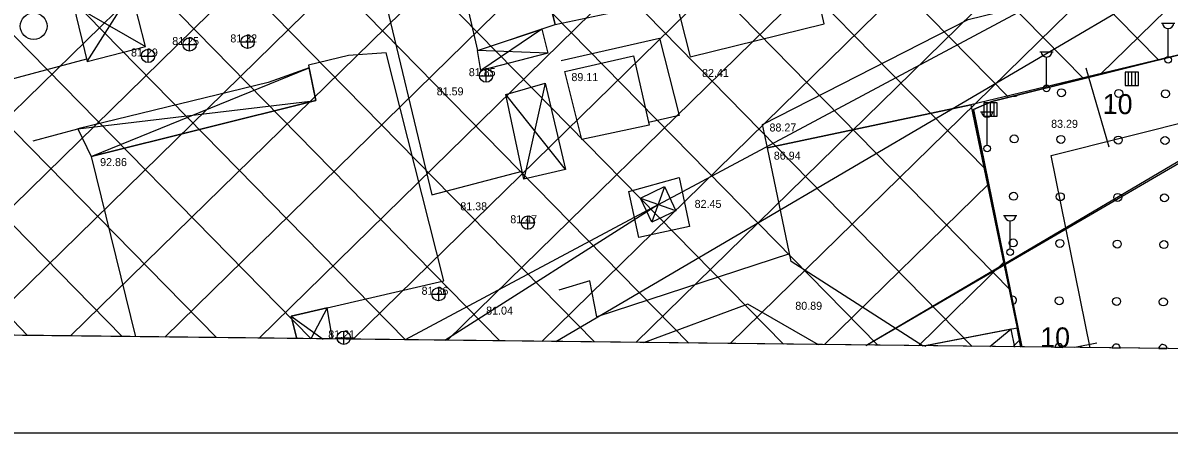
# Model space of a CAD drawing. Extents: x 412225 to 413380, y 4456471 to 4457189.
# Drawn here: x 412361 to 412532.8, y 4456471.2 to 4456532.7 of the extents above; entities that cross this region are included whole.
import ezdxf

# ---------------------------------------------------------------- set-up
doc = ezdxf.new("R2010")
doc.units = 0
for name, color, linetype in [('0_HALİHAZIR', 7, 'Continuous'), ('0_KADASTRO', 7, 'Continuous'), ('0_ÇERÇEVE', 7, 'Continuous'), ('HAT_ENERJI_NAKIL_HAT', 7, 'Continuous'), ('KST_ENERJI_NAKIL_HAT', 7, 'Continuous'), ('Level 33', 7, 'Continuous'), ('Level 35', 7, 'Continuous'), ('ROL_CEPHE', 7, 'Continuous'), ('SINIR_FONKSIYON', 7, 'Continuous'), ('SINIR_YAPIYAK', 7, 'Continuous')]:
    doc.layers.add(name, color=color, linetype=linetype)

msp = doc.modelspace()

# ---------------------------------------------------------------- linework, layer by layer
at = {"layer": '0_HALİHAZIR'}
for p, q in [((412370.66, 4456526.93), (412377.33, 4456537.43)), ((412368.61, 4456535.37), (412379.42, 4456529.15)), ((412438.8, 4456531.78), (412429.69, 4456525.54)), ((412531.69, 4456532.65), (412533.69, 4456532.65)), ((412532.69, 4456527.65), (412532.69, 4456531.84)), ((412386.02, 4456528.46), (412386.02, 4456530.46)), ((412394.73, 4456528.85), (412394.73, 4456530.85)), ((412379.81, 4456526.74), (412379.81, 4456528.74)), ((412385, 4456529.45), (412387, 4456529.45)), ((412393.71, 4456529.84), (412395.71, 4456529.84)), ((412439.71, 4456528.18), (412429.15, 4456528.55)), ((412513.47, 4456528.38), (412515.47, 4456528.38)), ((412378.79, 4456527.73), (412380.79, 4456527.73)), ((412514.47, 4456523.38), (412514.47, 4456527.58)), ((412371.27, 4456512.65), (412403.93, 4456525.96)), ((412429.46, 4456524.78), (412431.46, 4456524.78)), ((412430.48, 4456523.79), (412430.48, 4456525.79)), ((412528.27, 4456525.3), (412526.27, 4456525.3)), ((412526.27, 4456525.3), (412526.27, 4456523.3)), ((412528.27, 4456525.3), (412526.27, 4456525.3)), ((412526.27, 4456525.3), (412526.27, 4456523.3)), ((412526.77, 4456523.3), (412526.77, 4456525.3)), ((412527.27, 4456523.3), (412527.27, 4456525.3)), ((412527.81, 4456523.3), (412527.81, 4456525.3)), ((412528.27, 4456523.3), (412528.27, 4456525.3)), ((412528.27, 4456523.3), (412528.27, 4456525.3)), ((412439.31, 4456523.65), (412436.13, 4456509.27)), ((412526.27, 4456523.3), (412528.27, 4456523.3)), ((412526.27, 4456523.3), (412528.27, 4456523.3)), ((412442.34, 4456510.69), (412433.44, 4456521.98)), ((412369.25, 4456516.79), (412404.96, 4456521.05)), ((412507.05, 4456520.71), (412505.05, 4456520.71)), ((412505.05, 4456520.71), (412505.05, 4456518.71)), ((412507.05, 4456520.71), (412505.05, 4456520.71)), ((412505.05, 4456520.71), (412505.05, 4456518.71)), ((412505.55, 4456518.71), (412505.55, 4456520.71)), ((412506.05, 4456518.71), (412506.05, 4456520.71)), ((412506.59, 4456518.71), (412506.59, 4456520.71)), ((412507.05, 4456518.71), (412507.05, 4456520.71)), ((412507.05, 4456518.71), (412507.05, 4456520.71)), ((412504.57, 4456519.36), (412506.57, 4456519.36)), ((412505.05, 4456518.71), (412507.05, 4456518.71)), ((412505.05, 4456518.71), (412507.05, 4456518.71)), ((412505.57, 4456514.36), (412505.57, 4456518.56)), ((412457.22, 4456508.09), (412455.31, 4456502.88)), ((412453.58, 4456506.43), (412458.84, 4456504.54)), ((412435.71, 4456502.72), (412437.71, 4456502.72)), ((412436.73, 4456501.73), (412436.73, 4456503.73)), ((412508.02, 4456503.8), (412510.02, 4456503.8)), ((412509.02, 4456498.8), (412509.02, 4456502.99)), ((412423.36, 4456491), (412423.36, 4456493)), ((412422.34, 4456491.99), (412424.34, 4456491.99)), ((412401.23, 4456488.71), (412406.03, 4456485.28)), ((412406.65, 4456489.97), (412404.17, 4456485.3)), ((412408.12, 4456485.46), (412410.12, 4456485.46)), ((412409.14, 4456484.47), (412409.14, 4456486.47)), ((412509.18, 4456486.76), (412505.98, 4456484.11)), ((412496.23, 4456484.26), (412496.36, 4456484.23))]:
    msp.add_line(p, q, dxfattribs=at)
for points in [[(412401.21, 4456594.85), (412415.06, 4456539.7), (412414.66, 4456538.87), (412422.31, 4456506.91), (412435.88, 4456510.46)], [(412424.21, 4456594.58), (412427.64, 4456579.17), (412429.04, 4456579.59), (412440.8, 4456532.45), (412458.84, 4456536.33), (412461.04, 4456527.62), (412481.15, 4456532.54), (412479.12, 4456541.46), (412491.17, 4456544.37), (412482.53, 4456579.78), (412488.75, 4456581.68), (412486.01, 4456593.59), (412479.39, 4456592.17), (412478.97, 4456593.94)], [(412456.28, 4456505.44), (412618.62, 4456592.3)], [(412370.58, 4456527.26), (412358.28, 4456523.98), (412354.88, 4456537.05), (412367.01, 4456539.87)], [(412441.72, 4456527.05), (412456.45, 4456530.43), (412459.38, 4456518.79), (412454.81, 4456517.76)], [(412402.1, 4456485.33), (412401.23, 4456488.71), (412424.11, 4456494.03), (412415.48, 4456528.2), (412409.83, 4456527.79), (412403.84, 4456526.35), (412404.96, 4456521.05), (412371.27, 4456512.65), (412377.89, 4456485.61)], [(412495.96, 4456484.23), (412476.18, 4456496.93), (412472.63, 4456513.97), (412503.11, 4456520.4), (412510.06, 4456486.93), (412496.09, 4456484.23)], [(412362.58, 4456515.02), (412369.25, 4456516.79)], [(412487.38, 4456484.33), (412543.87, 4456517.66)], [(412457.2, 4456508.14), (412458.91, 4456504.52), (412455.29, 4456502.81), (412453.58, 4456506.43), (412457.2, 4456508.14)], [(412456.28, 4456505.44), (412418.33, 4456485.14)], [(412456.28, 4456505.44), (412424.28, 4456485.07)], [(412475.95, 4456498.06), (412447.06, 4456488.63), (412445.99, 4456494.01), (412441.36, 4456492.61)], [(412480.26, 4456484.41), (412469.68, 4456490.5), (412454.06, 4456484.72)], [(412407.42, 4456485.27), (412406.65, 4456489.97), (412401.23, 4456488.71), (412402.1, 4456485.33)], [(412510.63, 4456484.06), (412510.06, 4456486.93)], [(412509.73, 4456484.07), (412509.18, 4456486.76), (412496.23, 4456484.26), (412496.25, 4456484.23)]]:
    msp.add_lwpolyline(points, dxfattribs=at)
for points in [[(412429.15, 4456528.55), (412440.8, 4456532.45), (412431.3, 4456570.53), (412420.25, 4456567.34)], [(412472.63, 4456513.97), (412471.89, 4456517.48), (412502.72, 4456533.23), (412536.11, 4456541.4), (412544.04, 4456539.97), (412539.34, 4456529.12), (412503.11, 4456520.4)], [(412368.61, 4456535.37), (412370.66, 4456526.93), (412379.42, 4456529.15), (412377.33, 4456537.43)], [(412438.8, 4456531.78), (412439.71, 4456528.18), (412429.69, 4456525.54), (412429.15, 4456528.55)], [(412442.24, 4456525.39), (412452.57, 4456527.78), (412454.9, 4456517.35), (412444.8, 4456515.19)], [(412369.25, 4456516.79), (412371.27, 4456512.65), (412404.96, 4456521.05), (412403.93, 4456525.96), (412397.8, 4456523.74)], [(412433.44, 4456521.98), (412439.31, 4456523.65), (412442.34, 4456510.69), (412436.13, 4456509.27)], [(412451.87, 4456507.41), (412459.39, 4456509.49), (412460.94, 4456502.16), (412453.33, 4456500.49)]]:
    msp.add_lwpolyline(points, close=True, dxfattribs=at)
for centre, radius in [((412362.65, 4456532.21), 2), ((412386.01, 4456529.47), 1), ((412394.72, 4456529.86), 1), ((412379.8, 4456527.75), 1), ((412532.69, 4456527.15), 0.5), ((412430.46, 4456524.8), 1), ((412514.47, 4456522.88), 0.5), ((412505.57, 4456513.86), 0.5), ((412436.72, 4456502.74), 1), ((412509.02, 4456498.3), 0.5), ((412423.35, 4456492.01), 1), ((412409.13, 4456485.48), 1)]:
    msp.add_circle(centre, radius, dxfattribs=at)
for centre in [(412532.69, 4456532.68), (412514.47, 4456528.41), (412505.57, 4456519.39), (412509.02, 4456503.83)]:
    msp.add_arc(centre, 0.837, 183.298, 356.9072, dxfattribs=at)
at = {"layer": '0_KADASTRO'}
for points in [[(412510.76, 4456484.1), (412503.54, 4456519.73), (412506.28, 4456520.92), (412539.52, 4456529.23), (412570.45, 4456508.61), (412569.43, 4456508.33), (412571.22, 4456501.56), (412577.89, 4456503.67), (412588.02, 4456497.15), (412590.92, 4456495.2), (412585.15, 4456483.24)], [(412539.52, 4456529.23), (412506.28, 4456520.92), (412503.54, 4456519.73), (412510.76, 4456484.1)], [(412510.76, 4456484.1), (412356.53, 4456485.88)], [(412585.15, 4456483.24), (412510.76, 4456484.1)]]:
    msp.add_lwpolyline(points, dxfattribs=at)
at = {"layer": '0_ÇERÇEVE'}
for points in [[(412231.94, 4457188.94), (413313.94, 4457188.94), (413313.94, 4456471.18), (412231.94, 4456471.18)], [(412246.74, 4457181.27), (413310.43, 4457168.98), (413302.46, 4456474.95), (412238.67, 4456487.24)]]:
    msp.add_lwpolyline(points, close=True, dxfattribs=at)
at = {"layer": 'HAT_ENERJI_NAKIL_HAT'}
msp.add_line((412487.49, 4456484.37), (412772.52, 4456650.71), dxfattribs=at)
at = {"layer": 'KST_ENERJI_NAKIL_HAT'}
msp.add_line((412440.9, 4456484.9), (412669.03, 4456618.99), dxfattribs=at)
at = {"layer": 'Level 33'}
for points in [[(412515.7, 4456484.04), (412516.9, 4456484.03)], [(412524.3, 4456483.94), (412525.5, 4456483.93)], [(412531.3, 4456483.86), (412532.5, 4456483.85)]]:
    msp.add_lwpolyline(points, dxfattribs=at)
for centre in [(412516.69, 4456522.22), (412525.29, 4456522.13), (412532.29, 4456522.06), (412509.62, 4456515.29), (412516.62, 4456515.22), (412525.22, 4456515.13), (412532.22, 4456515.06), (412509.53, 4456506.69), (412516.53, 4456506.62), (412525.13, 4456506.53), (412532.13, 4456506.46), (412509.46, 4456499.69), (412516.46, 4456499.62), (412525.06, 4456499.53), (412532.06, 4456499.46), (412516.37, 4456491.02), (412524.97, 4456490.93), (412531.97, 4456490.86)]:
    msp.add_circle(centre, 0.6, dxfattribs=at)
for centre, start, end in [((412509.69, 4456522.29), 251.267, 316.8055), ((412509.37, 4456491.09), 279.0178, 103.8915), ((412516.3, 4456484.02), 0.3006, 178.3752), ((412524.9, 4456483.93), 359.2148, 179.4609), ((412531.9, 4456483.86), 358.331, 180.3447)]:
    msp.add_arc(centre, 0.6, start, end, dxfattribs=at)
at = {"layer": 'Level 35'}
for p, q in [((412355.84, 4456487.65), (412566.39, 4456693.93)), ((412368.18, 4456485.74), (412576.92, 4456690.25)), ((412351.91, 4456497.8), (412546.52, 4456688.47)), ((412340.38, 4456500.51), (412526.94, 4456683.28)), ((412382.31, 4456485.58), (412583.91, 4456683.1)), ((412396.43, 4456485.42), (412590.9, 4456675.95)), ((412410.55, 4456485.25), (412597.88, 4456668.79)), ((412424.67, 4456485.09), (412604.86, 4456661.62)), ((412531.23, 4456527.16), (412407, 4456653.96)), ((412438.8, 4456484.93), (412612.59, 4456655.2)), ((412519.99, 4456524.35), (412395.7, 4456651.21)), ((412508.74, 4456521.54), (412384.39, 4456648.46)), ((412452.92, 4456484.76), (412620.47, 4456648.92)), ((412505.37, 4456510.69), (412373.11, 4456645.69)), ((412509.02, 4456492.67), (412361.83, 4456642.91)), ((412467.04, 4456484.6), (412628.34, 4456642.63)), ((412503.34, 4456484.18), (412350.54, 4456640.14)), ((412489.18, 4456484.35), (412339.26, 4456637.36)), ((412522.55, 4456524.99), (412636.22, 4456636.35)), ((412475.02, 4456484.51), (412327.98, 4456634.59)), ((412460.86, 4456484.67), (412316.7, 4456631.82)), ((412446.7, 4456484.84), (412305.41, 4456629.04)), ((412432.54, 4456485), (412294.13, 4456626.27)), ((412418.38, 4456485.16), (412283.73, 4456622.6)), ((412404.22, 4456485.33), (412275.32, 4456616.9)), ((412390.06, 4456485.49), (412267.11, 4456610.99)), ((412375.9, 4456485.66), (412263.5, 4456600.38)), ((412481.16, 4456484.44), (412505.8, 4456508.58)), ((412495.29, 4456484.28), (412508.17, 4456496.9)), ((412361.74, 4456485.82), (412353.16, 4456494.58)), ((412509.41, 4456484.11), (412510.53, 4456485.21))]:
    msp.add_line(p, q, dxfattribs=at)
at = {"layer": 'SINIR_FONKSIYON'}
msp.add_lwpolyline([(412510.76, 4456484.1), (412503.54, 4456519.73), (412506.28, 4456520.92), (412539.52, 4456529.23), (412570.45, 4456508.61), (412577.89, 4456503.67), (412588.02, 4456497.15), (412590.38, 4456495.56)], dxfattribs=at)
msp.add_lwpolyline([(412510.76, 4456484.1), (412503.54, 4456519.73), (412506.28, 4456520.92), (412539.52, 4456529.23), (412570.45, 4456508.61), (412577.89, 4456503.67), (412588.02, 4456497.15), (412590.38, 4456495.56)], dxfattribs=at)
at = {"layer": 'SINIR_YAPIYAK'}
for p, q in [((412523.86, 4456514.05), (412520.4, 4456525.9)), ((412523.86, 4456514.05), (412520.4, 4456525.9)), ((412522.02, 4456484.68), (412518.7, 4456484)), ((412522.02, 4456484.68), (412518.7, 4456484))]:
    msp.add_line(p, q, dxfattribs=at)
msp.add_lwpolyline([(412520.99, 4456483.98), (412515.14, 4456512.83), (412537.65, 4456518.46), (412564.91, 4456500.28), (412572.42, 4456495.3), (412579.35, 4456490.84)], dxfattribs=at)
msp.add_lwpolyline([(412520.99, 4456483.98), (412515.14, 4456512.83), (412537.65, 4456518.46), (412564.91, 4456500.28), (412572.42, 4456495.3), (412579.35, 4456490.84)], dxfattribs=at)

# ---------------------------------------------------------------- texts
at = {"layer": '0_HALİHAZIR'}
for s, p in [('81.25', (412383.42, 4456529.38)), ('81.32', (412392.13, 4456529.77)), ('81.29', (412377.24, 4456527.66)), ('81.85', (412427.87, 4456524.71)), ('89.11', (412443.25, 4456523.97)), ('82.41', (412462.83, 4456524.58)), ('81.59', (412423.06, 4456521.83)), ('83.29', (412515.15, 4456516.96)), ('88.27', (412472.94, 4456516.41)), ('86.94', (412473.59, 4456512.19)), ('92.86', (412372.61, 4456511.22)), ('82.45', (412461.72, 4456504.95)), ('81.38', (412426.6, 4456504.59)), ('81.47', (412434.09, 4456502.65)), ('81.36', (412420.79, 4456491.92)), ('80.89', (412476.81, 4456489.67)), ('81.04', (412430.47, 4456488.95)), ('81.21', (412406.8, 4456485.39))]:
    msp.add_text(s, height=1.2, dxfattribs=at).set_placement(p)
at = {"layer": 'ROL_CEPHE'}
for p in [(412522.88, 4456519.05), (412522.88, 4456519.05), (412513.5, 4456484.06), (412513.5, 4456484.06)]:
    msp.add_text('10', height=3, rotation=359.4136, dxfattribs=at).set_placement(p)

doc.saveas('drawing.dxf')
